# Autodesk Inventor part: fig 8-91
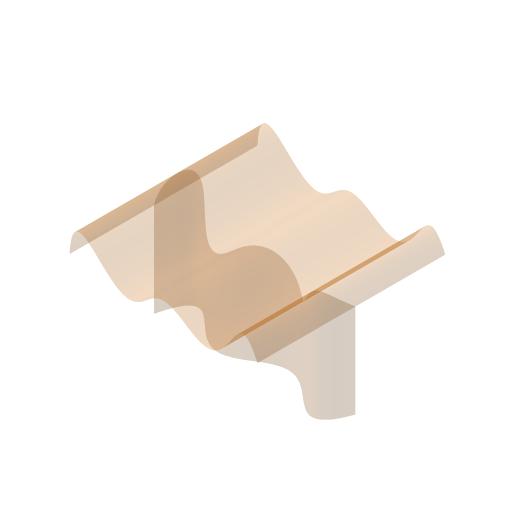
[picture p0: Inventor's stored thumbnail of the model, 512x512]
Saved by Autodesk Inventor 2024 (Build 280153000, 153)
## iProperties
Shininess: 64.0
Length Units: 11269
Angle Units: 11279
Time Units: 11290
Mass Units: 11283
Length Display Precision: 3
Angle Display Precision: 2
Compacted: True
Part Number: fig 8-91
Document SubType Name: Modeling
Created: 2003-08
Designer: Owner
Manufacturer: Standard
Standards Organization: Custom
Density: 1 g/cm^3
Material: Generic
Appearance: Default
Density: 0.0
Volumn: 0.0
Area: 0.0
PropertySet Name: Model Information
Control State: 0
Master: False
Checked Out: False
Author: Owner
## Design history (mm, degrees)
sketch "Sketch1"
  geometry: 7 further points
  constraints: 7 other
  dimensions: "d0" = 80 horizontal distance of point (40, 1.742) point (-40, -4.065); "d1" = 40 horizontal distance of point (0, 0) point (-40, -4.065)
extrude_surface "ExtrusionSrf1" sketch "Sketch1" dims "d2" = 80, "d3" = 0
sketch "Sketch2"
  geometry: L1 (40, 0)-(40, -40) reference; L2 (-40, 0)-(-40, -40) reference; 7 further points
  constraints: 2 point on line, 7 other
extrude_surface "ExtrusionSrf2" sketch "Sketch2" dims "d4" = 80, "d5" = 0
sketch "Sketch4"
  geometry: L1 (52.956, 12.425)-(-10.974, 12.425); A1 r 27.841 centre (-10.974, -15.416) between (-10.974, 12.425) and (-7.259, -43.008)
  constraints: 2 end point, 2 point on circle, 1 centre point, 1 horizontal, 1 tangent
feature "Trim1"
sketch "Sketch3"
  geometry: 2 further points
  constraints: 4 other
body "Srf1"
body "Srf2"
